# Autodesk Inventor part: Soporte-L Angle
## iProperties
Created: 2008-01
Part Number: Soporte-L Angle
Document SubType Name: Modeling
Designer: eruiz-tagle
Mass: 2.53606 g
Surface Area: 49.5413 cm^2
Volume: 2.53606 cm^3
Density: 1 g/cm^3
Author: eruiz-tagle
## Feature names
1. Extrusion1
2. Fillet1
3. Fillet2
4. Extrusion3
5. Rectangular Pattern1
6. Extrusion4
7. Rectangular Pattern2
8. Extrusion6
9. Rectangular Pattern4
10. Mirror2
11. Extrusion7
12. Extrusion8
13. Extrusion9
14. Extrusion10
15. Mirror3
16. Fillet3
17. Fillet4
